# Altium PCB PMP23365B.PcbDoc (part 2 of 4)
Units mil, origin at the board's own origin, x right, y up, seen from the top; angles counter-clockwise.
Board outline 5450 x 2600 mil, 4 copper layers (Top Layer, Signal Layer 1, Signal Layer 2, Bottom Layer), stack 61.2 mil thick; 303 components, 149 nets, 783 pads, 285 vias.
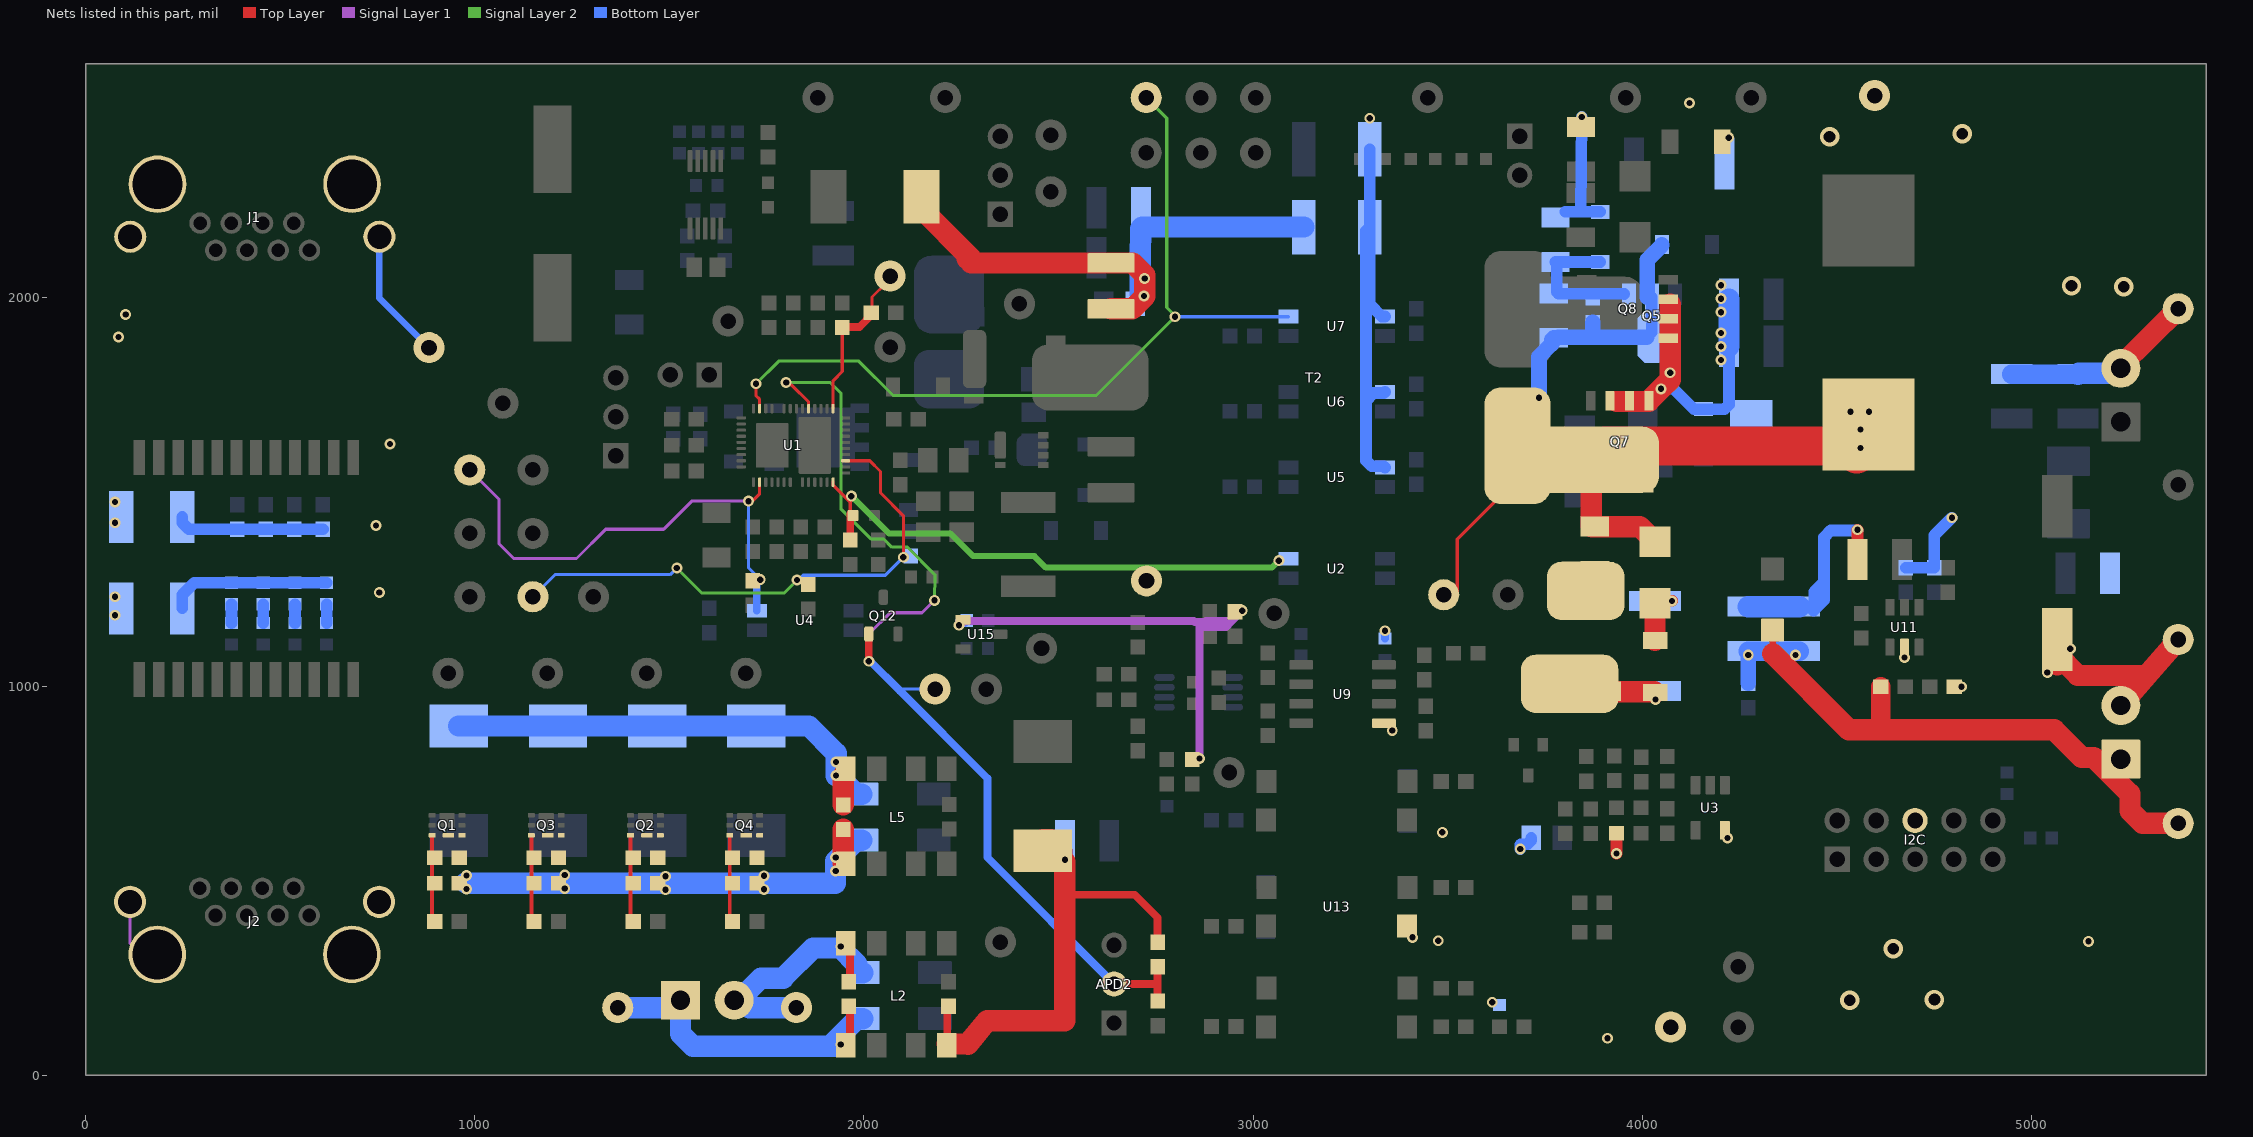
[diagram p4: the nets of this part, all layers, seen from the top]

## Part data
"5V Out" Adapter: "Terminal Block, 3.5mm Pitch, 2x1, TH", Color=Grey, Current_A=6A, Manufacturer="On-Shore Technology", PartNumber=ED555/2DS, Supplier Part Number 1=ED1514-ND, Voltage_V=150V
5V_REG VLOAD: library part CMP-0055137-2, "Test Point, Miniature, Red, TH", Color=Red, Manufacturer="Keystone Electronics", PartNumber=5000, Supplier Part Number 1=36-5000-ND
ad+ PR12: library part CMP-0055137-1, "Test Point, Miniature, Red, TH", Color=Red, Manufacturer=Keystone, Supplier Part Number 1=36-5000-ND
ad- EARTH PR36: library part CMP-0055138-1, "Test Point, Miniature, Black, TH", Color=Black, Manufacturer=Keystone, Supplier Part Number 1=36-5001-ND
APD1 BT DEN LUV PR45 REF SCL_at_pri SCL_pri SCL_pri_raw SDA_at_pri SDA_pri SDA_pri_raw TPH TPL: library part CMP-0055139-1, "Test Point, Miniature, White, TH", Color=White, Manufacturer=Keystone, Supplier Part Number 1=36-5002-ND
APD2 DIT I2C_pri: library part CMP-0054951-1, "Header, 100mil, 3x1, Tin, TH", Manufacturer="TE Connectivity", Supplier Part Number 1=5-146278-3-ND
C1 C2 C3 C4: library part CMP-0007468-5, "CAP, CERM, 0.01 uF, 100 V, +/- 10%, X7R, 0603", Cap_Case=0603, Manufacturer=MuRata, PartNumber=GRM188R72A103KA01D, Supplier Part Number 1=GRM188R72A103KA01D-ND, TempCo=X7R, Tolerance_%=10%, Value1=Unknown, Value2=100V, ValueDisplayed=0.01uF
C5 C6: library part CMP-0009438-2, "CAP, CERM, 1000 pF, 2000 V, +/- 10%, X7R, 1812", Cap_Case=1812, Manufacturer=MuRata, TempCo=X7R, Tolerance_%=10%, Value1=Unknown, Value2=2000V, ValueDisplayed=1000pF
C7 C8 C10 C11: library part CMP-0007053-4, "CAP, CERM, 1000 pF, 100 V, +/- 10%, X7R, 0603", Cap_Case=0603, Manufacturer=TDK, Supplier Part Number 1=445-1298-1-ND, TempCo=X7R, Tolerance_%=10%, Value1=Unknown, Value2=100V, ValueDisplayed=1000pF
C9: library part CMP-0009232-2, "CAP, CERM, 2.2 uF, 100 V, +/- 10%, X7R, 1210", Cap_Case=1210, Manufacturer=MuRata, PartNumber=GRM32ER72A225KA35L, Supplier Part Number 1=490-3385-1-ND, TempCo=X7R, Tolerance_%=10%, Value1="0.007 ohm", Value2=100V, ValueDisplayed=2.2uF
C12 C13 C14 C15: library part CMP-0007209-4, "CAP, CERM, 330 pF, 50 V, +/- 5%, C0G/NP0, 0603", Cap_Case=0603, Manufacturer=MuRata, Supplier Part Number 1=490-1439-1-ND, TempCo=C0G/NP0, Tolerance_%=5%, Value1=Unknown, Value2=50V, ValueDisplayed=330pF
C16 C18: library part CMP-0009358-2, "CAP, CERM, 2200 pF, 2000 V, +/- 10%, X7R, 1812", Cap_Case=1812, Manufacturer=TDK, Supplier Part Number 1=445-2389-1-ND, TempCo=X7R, Tolerance_%=10%, Value1=Unknown, Value2=2000V, ValueDisplayed=2200pF
C17 C31 C40: library part CMP-0008975-2, "CAP, CERM, 0.047 uF, 250 V, +/- 10%, X7R, 1206", Cap_Case=1206, Manufacturer=MuRata, Supplier Part Number 1=490-3538-1-ND, TempCo=X7R, Tolerance_%=10%, Value1=Unknown, Value2=250V, ValueDisplayed=0.047uF
C19: library part CMP-0009053-2, "CAP, CERM, 470 pF, 500 V, +/- 10%, X7R, 1206", Cap_Case=1206, Manufacturer=Vishay-Vitramon, Supplier Part Number 1=720-1076-1-ND, TempCo=X7R, Tolerance_%=10%, Value1=Unknown, Value2=500V, ValueDisplayed=470pF
C20 C33: library part CMP-0008881-2, "CAP, CERM, 0.1 uF, 100 V, +/- 10%, X7R, 1206", Cap_Case=1206, Manufacturer=MuRata, Supplier Part Number 1=490-3364-1-ND, TempCo=X7R, Tolerance_%=10%, Value1=Unknown, Value2=100V, ValueDisplayed=0.1uF
C21: library part CMP-0011231-3, "CAP, AL, 68 uF, 100 V, +/- 20%, SMD", Cap_Case=KE0, Manufacturer=Chemi-Con, Tolerance_%=20%, Value1=Unknown, Value2=100V, ValueDisplayed=68uF
C22 C23 C24: library part CMP-0009232-2, "CAP, CERM, 2.2 uF, 100 V, +/- 10%, X7R, 1210", Cap_Case=1210, Manufacturer=MuRata, Supplier Part Number 1=490-3385-1-ND, TempCo=X7R, Tolerance_%=10%, Value1="0.007 ohm", Value2=100V, ValueDisplayed=2.2uF
C25: library part CMP-0008363-2, "CAP, CERM, 0.1 uF, 100 V, +/- 10%, X7R, 0805", Cap_Case=0805, Manufacturer=MuRata, Supplier Part Number 1=490-12005-1-ND, TempCo=X7R, Tolerance_%=10%, Value1=Unknown, Value2=100V, ValueDisplayed=0.1uF
C26 C32 C44: library part CMP-0007130-4, "CAP, CERM, 100 pF, 100 V, +/- 5%, C0G/NP0, AEC-Q200 Grade 1, 0603", Cap_Case=0603, Manufacturer=MuRata, Supplier Part Number 1=490-4771-1-ND, TempCo=C0G/NP0, Tolerance_%=5%, Value1=Unknown, Value2=100V, ValueDisplayed=100pF
C27 C29 C55 C56 C57 C62: library part CMP-0009214-2, "CAP, CERM, 10 uF, 50 V, +/- 10%, X5R, 1210", Cap_Case=1210, Manufacturer=MuRata, Supplier Part Number 1=490-8590-1-ND, TempCo=X5R, Tolerance_%=10%, Value1=Unknown, Value2=50V, ValueDisplayed=10uF
C30: library part CMP-0008336-2, "CAP, CERM, 1 uF, 25 V, +/- 10%, X7R, 0805", Cap_Case=0805, Manufacturer=MuRata, Supplier Part Number 1=GRM21BR71E105KA99L-ND, TempCo=X7R, Tolerance_%=10%, Value1=Unknown, Value2=25V, ValueDisplayed=1uF
C34 C48: library part CMP-0007457-4, "CAP, CERM, 0.047 uF, 50 V, +/- 10%, X7R, 0603", Cap_Case=0603, Manufacturer=MuRata, Supplier Part Number 1=490-3287-1-ND, TempCo=X7R, Tolerance_%=10%, Value1=Unknown, Value2=50V, ValueDisplayed=0.047uF
C35: library part CMP-0009046-1, "CAP, CERM, 220 pF, 500 V, +/- 10%, X7R, 1206", Cap_Case=1206, Manufacturer=Vishay-Vitramon, Supplier Part Number 1=720-1023-1-ND, TempCo=X7R, Tolerance_%=10%, Value1=Unknown, Value2=500V, ValueDisplayed=220pF
C36: library part CMP-0007885-1, "CAP, CERM, 4.7 uF, 35 V, +/- 10%, X7R, 0805", Cap_Case=0805, Manufacturer=TDK, Supplier Part Number 1=445-7555-1-ND, TempCo=X7R, Tolerance_%=10%, Value1="0.002346 ohm", Value2=35V, ValueDisplayed=4.7uF
C37: library part CMP-0008021-2, "CAP, CERM, 0.1 uF, 50 V, +/- 10%, X7R, AEC-Q200 Grade 1, 0805", Cap_Case=0805, Manufacturer=MuRata, Supplier Part Number 1=490-8049-1-ND, TempCo=X7R, Tolerance_%=10%, Value1=Unknown, Value2=50V, ValueDisplayed=0.1uF
C38: library part CMP-0007835-2, "CAP, CERM, 0.22 uF, 50 V, +/- 10%, X5R, 0805", Cap_Case=0805, Manufacturer=TDK, Supplier Part Number 1=445-14405-1-ND, TempCo=X5R, Tolerance_%=10%, Value1="0.016949 ohm", Value2=50V, ValueDisplayed=0.22uF
C39 C42: library part CMP-0007077-5, "CAP, CERM, 0.1 uF, 25 V, +/- 10%, X7R, AEC-Q200 Grade 1, 0603", Cap_Case=0603, Manufacturer=TDK, Supplier Part Number 1=445-5667-1-ND, TempCo=X7R, Tolerance_%=10%, Value1=Unknown, Value2=25V, ValueDisplayed=0.1uF
C41: library part CMP-0006897-4, "CAP, CERM, 2200 pF, 50 V, +/- 10%, X7R, 0603", Cap_Case=0603, Manufacturer=Kemet, Supplier Part Number 1=1362428, TempCo=X7R, Tolerance_%=10%, Value1=Unknown, Value2=50V, ValueDisplayed=2200pF
C43: library part CMP-0007220-4, "CAP, CERM, 47 pF, 50 V, +/- 5%, C0G/NP0, 0603", Cap_Case=0603, Manufacturer=MuRata, Supplier Part Number 1=490-1419-1-ND, TempCo=C0G/NP0, Tolerance_%=5%, Value1=Unknown, Value2=50V, ValueDisplayed=47pF
C45: library part CMP-0094554-1, "Multilayer Ceramic Capacitors 68nF ±20% 25V X8R SMD 0603", Manufacturer=TDK, Operating Temperature Range="-55°C to +150°C", TempCo=0.15, Temperature Characteristic=X8R, Tolerance_%=0.2%, ValueDisplayed=68nF, Voltage=50V
C46: library part CMP-0006978-4, "CAP, CERM, 0.01 uF, 50 V, +/- 10%, X7R, 0603", Cap_Case=0603, Manufacturer=Kemet, Supplier Part Number 1=399-5346-1-ND, TempCo=X7R, Tolerance_%=10%, Value1=Unknown, Value2=50V, ValueDisplayed=0.01uF
C47: library part CMP-0007873-2, "CAP, CERM, 1 uF, 50 V, +/- 10%, X7R, 0805", Cap_Case=0805, Manufacturer=TDK, Supplier Part Number 1=445-7547-1-ND, TempCo=X7R, Tolerance_%=10%, Value1="0.008782 ohm", Value2=50V, ValueDisplayed=1uF
C49 C61: library part CMP-0006837-3, "CAP, CERM, 0.1 uF, 50 V, +/- 10%, X7R, 0603", Cap_Case=0603, Manufacturer="Wurth Elektronik", TempCo=X7R, Tolerance_%=10%, Value1=Unknown, Value2=50V, ValueDisplayed=0.1uF
C51 C52 C53 C65 C66 C67 C68 C70: library part CMP-0079720-1, "CAP, CERM, 1 µF, 25 V,+/- 10%, X7R, 0603", Cap_Case=0603, Manufacturer=MuRata, Supplier Part Number 1=490-10888-1-ND, TempCo=X7R, Tolerance_%=10%, Value2=25V, ValueDisplayed=1µF
C58: library part CMP-0064994-2, "CAP, Polymer Hybrid, 100 uF, 50 V,+/- 20%, 0.028 ohm, AEC-Q200 Grade 1, D10xL10.2mm SMD", Cap_Case=10x10.2mm, Manufacturer=Panasonic, Supplier Part Number 1=P15462CT-ND, Tolerance_%=20%, Value1="0.028 ohm", Value2=50V, ValueDisplayed=100uF
C59 C60: library part CMP-0009224-2, "CAP, CERM, 22 uF, 25 V, +/- 10%, X7R, 1210", Cap_Case=1210, Manufacturer=MuRata, Supplier Part Number 1=490-5313-1-ND, TempCo=X7R, Tolerance_%=10%, Value1=Unknown, Value2=25V, ValueDisplayed=22uF
C63 C64: library part CMP-0007508-5, "CAP, CERM, 1 uF, 50 V, +/- 10%, X7R, 0603", Cap_Case=0603, Manufacturer="Taiyo Yuden", Supplier Part Number 1=587-3247-1-ND, TempCo=X7R, Tolerance_%=10%, Value1=Unknown, Value2=50V, ValueDisplayed=1uF
COMP CS DTHR SST VB: library part CMP-0055139-2, "Test Point, Miniature, White, TH", Color=White, Manufacturer="Keystone Electronics", Supplier Part Number 1=36-5002-ND
D1: library part CMP-0028411-1, "Diode, Schottky, 100 V, 3 A, SMC", Manufacturer="Diodes Inc.", Supplier Part Number 1=B3100-FDICT-ND, Value1=3A, Value2=0.79V
D2 D3 D4 D5: library part CMP-0028623-2, "Diode, Schottky, 100 V, 3 A, SMC", Manufacturer=Vishay-Semiconductor, Value1=3A, Value2=0.62V
D10: library part CMP-0005708-3, "Diode, TVS, Uni, 150 V, 243 Vc, SMC", Manufacturer="Micro Commercial Components", Value1=1500W
D11 D12 D19: library part CMP-0029023-2, "Diode, Superfast Rectifier, 150 V, 1 A, SMA", Manufacturer="Diodes Inc.", Value1=1A, Value2=0.92V
D13: library part CMP-0076993-2, "Diode, Fast Rectifier, 200 V, 0.8 A, SOD-123", Manufacturer=Rohm, Value1=0.8A, Value2=0.95V
D14 D15 D18 D21: library part CMP-0076981-2, "Diode, Switching, 100 V, 0.2 A, SOD-123", Manufacturer="ON Semiconductor", Value1=0.2A, Value2=V
D16 D17 D26: library part CMP-0005751-4, "Diode, Zener, 12 V, 500 mW, SOD-123", Manufacturer="Diodes Inc.", Power_W=500mW, Value1=0.5W
D22: library part CMP-0096356-1, "Diode Array 1 Pair Series Connection Schottky 70 V 200mA (DC) Surface Mount TO-236-3, SC-59, SOT-23-3", Digikey Part Number=BAS70-04-E3-18GICT-ND, Forward Current=200mA, Manufacturer=Vishay, Max Surge Forward Current=600mA, Mouser Part Number=78-BAS70-04-E3-18, Operating Temperature Range="-55°C to +125°C", Peak Reverse Current=0.02uA, ValueDisplayed=1.5pF
D23 D24 D25 D27: library part CMP-0002892-3, "LED, Yellow, SMD", Color=yellow, Manufacturer="Wurth Elektronik", Value1=W, Value2=2V
D29 D30: library part CMP-0080707-2, "Diode, Schottky, 20 V, 0.5 A, SOD-123", Manufacturer="Diodes Inc.", Value1=0.5A, Value2=0.33V
Drain_F Drain_M Drain_P Drain_R Gate_ex Gate_F Gate_M Gate_P Gate_R PR78: library part CMP-0055140-1, "Test Point, Miniature, Orange, TH", Color=Orange, Manufacturer=Keystone, Supplier Part Number 1=36-5003-ND
EMPS TPH/TPL/BT: library part CMP-0054952-1, "Header, 100mil, 2x1, Tin, TH", Manufacturer="TE Connectivity", Supplier Part Number 1=5-146278-2-ND
GND1 GND2 GND3 RTN1 RTN2 RTN3 VSS1 VSS2: library part CMP-0055138-2, "Test Point, Miniature, Black, TH", Color=Black, Manufacturer="Keystone Electronics", Supplier Part Number 1=36-5001-ND
GND4 RTN4: library part CMP-0055138-2, "Test Point, Miniature, Black, TH", Color=Black, Manufacturer="Keystone Electronics", PartNumber=5001, Supplier Part Number 1=36-5001-ND
H1 H2 H3 H4: library part CMP-0003620-1, "Bumpon, Hemisphere, 0.44 X 0.20, Clear", Manufacturer=3M, Supplier Part Number 1=SJ5303-7-ND
I2C: library part CMP-0055448-2, "Header (shrouded), 100mil, 5x2, High-Temperature, Gold, TH", Manufacturer=3M, Supplier Part Number 1=MHC10K-ND
J1 J2: library part CMP-0054918-1, "RJ45, No LED, tab up, R/A, TH", Color=Black, Manufacturer="TE Connectivity", Supplier Part Number 1=A97716-ND
L1 L3 L4 L6: library part CMP-0003134-1, "Ferrite Bead, 180 ohm @ 100 MHz, 3.1 A, 0805", Manufacturer="Wurth Elektronik", Supplier Part Number 1=732-6123-1-ND, Value1="0.0265 ohm", Value2=3.1A, ValueDisplayed="180 ohm"
L2 L5: library part CMP-0094039-1, "Common Mode Choke Power 700Ω 4A -40 to 125°C Wire Wound Surface Mount T/R", Digikey Part Number=240-2978-1-ND, Impedance At Frequency="700Ω @ 100MHz", Manufacturer=Laird, Mouser Part Number=739-CM7060P701R-10, Operating Temperature Range="-40°C to +125°C"
L7: library part CMP-0059863-1, "Inductor, Drum Core, Ferrite, 4.7 uH, 6.5 A, 0.023 ohm, SMD", Manufacturer=Cyntec, Value1="0.023 ohm", Value2=6.5A, ValueDisplayed=4.7uH
L8: library part CMP-0064480-2, "Inductor, Shielded Drum Core, Ferrite, 47 uH, 6.8 A, 0.0335 ohm, SMD", Manufacturer="Wurth Elektronik", Supplier Part Number 1=732-2179-1-ND, Value1="0.0335 ohm", Value2=6.8A, ValueDisplayed=47uH
L9: library part CMP-0061681-2, "Inductor, Drum Core, Ferrite, 1 mH, 0.1 A, 13.8 ohm, SMD", Manufacturer=Coilcraft, Value1="13.8 ohm", Value2=0.1A, ValueDisplayed=1mH
L10: library part CMP-0063313-2, "Inductor, Shielded Drum Core, Powdered Iron, 1 uH, 6.5 A, 0.011 ohm, SMD", Manufacturer=Vishay-Dale, Supplier Part Number 1=541-1234-1-ND, Value1="0.011 ohm", Value2=6.5A, ValueDisplayed=1uH
L11: library part CMP-0080041-1, "Inductor, Shielded, Ferrite, 15 µH, 2.4 A, 0.078 ohm, SMD", Manufacturer=MuRata, PartNumber=1273AS-H-150M{}P3, Supplier Part Number 1=490-10838-1-ND, Value1="0.078 ohm", Value2=2.4A, ValueDisplayed=15µH
Logo1: library part CMP-0074847-1, "FCC_disclaimer"
Logo2: library part CMP-0074769-1
OUT: library part CMP-0074913-1, "Terminal Block, 3.5mm Pitch, 2x1, TH", Color=Grey, Current_A=6A, Manufacturer="On-Shore Technology", Supplier Part Number 1=ED1514-ND, Voltage_V=150V
Q1 Q2 Q3 Q4: library part CMP-0000968-2, "MOSFET, N-CH, 100 V, 4.5 A, DQK0006C (WSON-6)", Alternate Manufacturer=None, Manufacturer="Texas Instruments"
Q5 Q6: library part CMP-0000510-2, "Transistor, NPN, 150 V, 1 A, AEC-Q101, SOT-89", Manufacturer="Diodes Inc.", Supplier Part Number 1=FCX495CT-ND, Value1="1 A", Value2=300
Q7 Q8: library part CMP-0001056-1, "MOSFET, N-CH, 150 V, 35 A, PQFN08A", Alternate Manufacturer=None, Manufacturer="Fairchild Semiconductor", Supplier Part Number 1=FDMS86200CT-ND, Value2="33 nC"
Q9: library part CMP-0000056-3, "MOSFET, P-CH, -150 V, -3 A, QFN-8", Alternate Manufacturer=None, Manufacturer="Fairchild Semiconductor", Value2="6.2 nC"
Q10: library part CMP-0001057-1, "MOSFET, N-CH, 150 V, 6.7 A, PQFN08A", Alternate Manufacturer=None, Manufacturer="Fairchild Semiconductor", Supplier Part Number 1=FDMS86250CT-ND, Value1=0.02, Value2="36 nC"
Q11: library part CMP-0000985-1, "MOSFET, N-CH, 100 V, 26 A, PowerPAK SO-8", Alternate Manufacturer=None, Manufacturer="Fairchild Semiconductor", Supplier Part Number 1=FDMS86105CT-ND, Value1=0.03, Value2="4.2 nC"
Q12: library part CMP-0000769-1, "MOSFET, N-CH, 60 V, 0.17 A, SOT-23", Alternate Manufacturer=None, Manufacturer="Diodes Inc.", Supplier Part Number 1=2N7002-FDICT-ND, Value1=7, Value2="223 nC"
R1 R2 R3 R4: library part CMP-0022590-4, "RES, 75.0, 1%, 0.1 W, AEC-Q200 Grade 0, 0603", Manufacturer=Vishay-Dale, PartNumber=CRCW060375R0FKEA, Power_W=100mW, Supplier Part Number 1=541-75.0HCT-ND, TempCo="100 ppm/C", Tolerance_%=1%, Value2=0.1W, Value_Code=75R0, ValueDisplayed=75.0
R5 R6 R7 R8: library part CMP-0023268-5, "RES, 75.0, 1%, 0.1 W, 0603", Manufacturer=Yageo, Power_W=100mW, Supplier Part Number 1=311-75.0HRCT-ND, TempCo="100 ppm/C", Tolerance_%=1%, Value2=0.1W, Value_Code=75R0, ValueDisplayed=75.0
R9 R12 R13 R18 R122: library part CMP-0020802-2, "RES, 0, 5%, 0.125 W, 0805", Manufacturer=Rohm, Power_W=125mW, Supplier Part Number 1=RHM0.0ARCT-ND, TempCo="400 ppm/C", Tolerance_%=5%, Value2=0.125W, Value_Code=0000, ValueDisplayed=0
R10 R59 R88: library part CMP-0021990-4, "RES, 100 k, 1%, 0.1 W, AEC-Q200 Grade 0, 0603", Manufacturer=Vishay-Dale, Power_W=100mW, Supplier Part Number 1=541-100KHCT-ND, TempCo="100 ppm/C", Tolerance_%=1%, Value2=0.1W, Value_Code=100k
R11 R31 R53 R54: library part CMP-0021998-4, "RES, 10.0 k, 1%, 0.1 W, AEC-Q200 Grade 0, 0603", Manufacturer=Vishay-Dale, Power_W=100mW, Supplier Part Number 1=541-10.0KHCT-ND, TempCo="100 ppm/C", Tolerance_%=1%, Value2=0.1W, Value_Code=10k0, ValueDisplayed=10.0k
R14 R15 R16 R17: "RES, 1.00 M, 1%, 0.1 W, AEC-Q200 Grade 0, 0603", Manufacturer=Vishay-Dale, PartNumber=CRCW06031M00FKEA, Power_W=100mW, Supplier Part Number 1=541-1.00MHCT-ND, TempCo="100 ppm/C", Tolerance_%=1%, Value2=0.1W, Value_Code=1M00, ValueDisplayed=1.00M
R19 R20 R21 R22: "RES, 232 k, 1%, 0.1 W, AEC-Q200 Grade 0, 0603", Manufacturer=Vishay-Dale, PartNumber=CRCW0603232KFKEA, Power_W=100mW, Supplier Part Number 1=541-232KHCT-ND, TempCo="100 ppm/C", Tolerance_%=1%, Value2=0.1W, Value_Code=232k
R23: library part CMP-0015944-1, "RES, 33 k, 5%, 1 W, AEC-Q200 Grade 0, 2512", Manufacturer=Vishay-Dale, Power_W=1W, Supplier Part Number 1=541-33KXCT-ND, TempCo="200 ppm/C", Tolerance_%=5%, Value_Code=33k0, ValueDisplayed=33k
R24: library part CMP-0015978-3, "RES, 51, 5%, 1 W, AEC-Q200 Grade 0, 2512", Manufacturer=Vishay-Dale, Power_W=1W, Supplier Part Number 1=541-51XCT-ND, TempCo="200 ppm/C", Tolerance_%=5%, Value_Code=51R0, ValueDisplayed=51
R25: library part CMP-0018576-1, "RES, 10 k, 5%, 0.25 W, 1206", Manufacturer=Vishay-Dale, Power_W=250mW, Supplier Part Number 1=541-10KECT-ND, TempCo="200 ppm/C", Tolerance_%=5%, Value2=0.25W, Value_Code=10k0, ValueDisplayed=10k
R26 R72 R73 R74 R75 R76 R101 R108 R109: library part CMP-0080488-1, "RES, 10.0 k, 1%, 0.1 W, 0603", Manufacturer="TT Electronics/IRC", Power_W=100mW, TempCo="100 ppm/C", Tolerance_%=1%, Value2=0.1W, Value_Code=10k0, ValueDisplayed=10.0k
R27: library part CMP-0018688-2, "RES, 4.3 k, 5%, 0.25 W, 1206", Manufacturer=Vishay-Dale, Power_W=250mW, Supplier Part Number 1=541-4.3KECT-ND, TempCo="200 ppm/C", Tolerance_%=5%, Value2=0.25W, Value_Code=4k30, ValueDisplayed=4.3k
R28: library part CMP-0016779-2, "RES, 20.0 k, 1%, 0.25 W, 1206", Manufacturer=Vishay-Dale, Power_W=250mW, Supplier Part Number 1=541-20.0KFCT-ND, TempCo="100 ppm/C", Tolerance_%=1%, Value2=0.25W, Value_Code=20k0, ValueDisplayed=20.0k
R29: library part CMP-0018659-1, "RES, 33, 5%, 0.25 W, 1206", Manufacturer=Vishay-Dale, Power_W=250mW, Supplier Part Number 1=541-33ECT-ND, TempCo="200 ppm/C", Tolerance_%=5%, Value2=0.25W, Value_Code=33R0, ValueDisplayed=33
R30: library part CMP-0022931-4, "RES, 237 k, 1%, 0.1 W, 0603", Manufacturer=Yageo, Power_W=100mW, Supplier Part Number 1=311-237KHRCT-ND, TempCo="100 ppm/C", Tolerance_%=1%, Value2=0.1W, Value_Code=237k
R32: library part CMP-0022532-4, "RES, 60.4 k, 1%, 0.1 W, AEC-Q200 Grade 0, 0603", Manufacturer=Vishay-Dale, Power_W=100mW, Supplier Part Number 1=541-60.4KHCT-ND, TempCo="100 ppm/C", Tolerance_%=1%, Value2=0.1W, Value_Code=60k4, ValueDisplayed=60.4k
R33: library part CMP-0015868-3, "RES, 10 k, 5%, 1 W, AEC-Q200 Grade 0, 2512", Manufacturer=Vishay-Dale, Power_W=1W, Supplier Part Number 1=541-10KXCT-ND, TempCo="200 ppm/C", Tolerance_%=5%, Value_Code=10k0, ValueDisplayed=10k
R34 R36: library part CMP-0025703-4, "RES, 10, 5%, 0.1 W, AEC-Q200 Grade 0, 0603", Manufacturer=Vishay-Dale, Power_W=100mW, Supplier Part Number 1=541-10GCT-ND, TempCo="200 ppm/C", Tolerance_%=5%, Value2=0.1W, Value_Code=10R0, ValueDisplayed=10
R35: library part CMP-0022447-4, "RES, 49.9 k, 1%, 0.1 W, AEC-Q200 Grade 0, 0603", Manufacturer=Vishay-Dale, Power_W=100mW, Supplier Part Number 1=541-49.9KHCT-ND, TempCo="100 ppm/C", Tolerance_%=1%, Value2=0.1W, Value_Code=49k9, ValueDisplayed=49.9k
R37: library part CMP-0023027-4, "RES, 31.6, 1%, 0.1 W, 0603", Manufacturer=Yageo, Power_W=100mW, Supplier Part Number 1=311-31.6HRCT-ND, TempCo="100 ppm/C", Tolerance_%=1%, Value2=0.1W, Value_Code=31R6, ValueDisplayed=31.6
R38: library part CMP-0023123-5, "RES, 45.3, 1%, 0.1 W, 0603", Manufacturer=Yageo, Power_W=100mW, Supplier Part Number 1=311-45.3HRCT-ND, TempCo="100 ppm/C", Tolerance_%=1%, Value2=0.1W, Value_Code=45R3, ValueDisplayed=45.3
R39: library part CMP-0082530-1, "RES, 100 k, 5%, 0.1 W, 0603", Manufacturer=Vishay-Dale, Power_W=100mW, Supplier Part Number 1=541-3992-1-ND, TempCo="200 ppm/C", Tolerance_%=5%, Value2=0.1W, Value_Code=100k
R40: library part CMP-0023000-5, "RES, 2.00 k, 1%, 0.1 W, 0603", Manufacturer=Yageo, Power_W=100mW, Supplier Part Number 1=311-2.00KHRCT-ND, TempCo="100 ppm/C", Tolerance_%=1%, Value2=0.1W, Value_Code=2k00, ValueDisplayed=2.00k
R41: library part CMP-0022965-5, "RES, 27.4 k, 1%, 0.1 W, 0603", Manufacturer=Yageo, Power_W=100mW, Supplier Part Number 1=311-27.4KHRCT-ND, TempCo="100 ppm/C", Tolerance_%=1%, Value2=0.1W, Value_Code=27k4, ValueDisplayed=27.4k
R42: library part CMP-0017281-2, "RES, 0.05, 1%, 1 W, AEC-Q200 Grade 0, 1206", Manufacturer=Panasonic, Power_W=1W, Supplier Part Number 1=P0.05BVCT-ND, TempCo="50 ppm/C", Tolerance_%=1%, Value_Code=R050, ValueDisplayed=0.05
R43: library part CMP-0022879-5, "RES, 1.47 k, 1%, 0.1 W, 0603", Manufacturer=Yageo, Power_W=100mW, Supplier Part Number 1=311-1.47KHRCT-ND, TempCo="100 ppm/C", Tolerance_%=1%, Value2=0.1W, Value_Code=1k47, ValueDisplayed=1.47k
R44 R45: library part CMP-0022458-2, "RES, 4.99 k, 1%, 0.1 W, 0603", Manufacturer=Vishay-Dale, Power_W=100mW, Supplier Part Number 1=541-4.99KHCT-ND, TempCo="100 ppm/C", Tolerance_%=1%, Value2=0.1W, Value_Code=4k99, ValueDisplayed=4.99k
R46: library part CMP-0022268-4, "RES, 2.00 k, 1%, 0.1 W, AEC-Q200 Grade 0, 0603", Manufacturer=Vishay-Dale, Power_W=100mW, Supplier Part Number 1=541-2.00KHCT-ND, TempCo="100 ppm/C", Tolerance_%=1%, Value2=0.1W, Value_Code=2k00, ValueDisplayed=2.00k
R47: library part CMP-0022410-4, "RES, 40.2 k, 1%, 0.1 W, AEC-Q200 Grade 0, 0603", Manufacturer=Vishay-Dale, Power_W=100mW, Supplier Part Number 1=541-40.2KHCT-ND, TempCo="100 ppm/C", Tolerance_%=1%, Value2=0.1W, Value_Code=40k2, ValueDisplayed=40.2k
R48 R55: library part CMP-0022544-4, "RES, 64.9 k, 1%, 0.1 W, AEC-Q200 Grade 0, 0603", Manufacturer=Vishay-Dale, Power_W=100mW, Supplier Part Number 1=541-64.9KHCT-ND, TempCo="100 ppm/C", Tolerance_%=1%, Value2=0.1W, Value_Code=64k9, ValueDisplayed=64.9k
R49 R98 R99 R104: library part CMP-0022109-5, "RES, 1.00 k, 1%, 0.1 W, AEC-Q200 Grade 0, 0603", Manufacturer=Vishay-Dale, Power_W=100mW, Supplier Part Number 1=541-1.00KHCT-ND, TempCo="100 ppm/C", Tolerance_%=1%, Value2=0.1W, Value_Code=1k00, ValueDisplayed=1.00k
R50: library part CMP-0022445-4, "RES, 499 k, 1%, 0.1 W, AEC-Q200 Grade 0, 0603", Manufacturer=Vishay-Dale, Power_W=100mW, Supplier Part Number 1=541-499KHCT-ND, TempCo="100 ppm/C", Tolerance_%=1%, Value2=0.1W, Value_Code=499k
R51: library part CMP-0022008-4, "RES, 110 k, 1%, 0.1 W, AEC-Q200 Grade 0, 0603", Manufacturer=Vishay-Dale, Power_W=100mW, Supplier Part Number 1=541-110KHCT-ND, TempCo="100 ppm/C", Tolerance_%=1%, Value2=0.1W, Value_Code=110k
R52: library part CMP-0023151-1, "RES, 4.64 k, 1%, 0.1 W, 0603", Manufacturer="Yageo America", Power_W=100mW, Supplier Part Number 1=311-4.64KHRCT-ND, TempCo="200 ppm/C", Tolerance_%=1%, Value2=0.1W, Value_Code=4k64, ValueDisplayed=4.64k
R60 R61 R62 R63 R64 R65 R95: library part CMP-0025753-1, "RES, 20 k, 5%, 0.1 W, 0603", Manufacturer=Vishay-Dale, Power_W=100mW, Supplier Part Number 1=541-20KGCT-ND, TempCo="200 ppm/C", Tolerance_%=5%, Value2=0.1W, Value_Code=20k0, ValueDisplayed=20k
R66: library part CMP-0021980-1, "RES, 0.01, 1%, 0.25 W, AEC-Q200 Grade 0, 0805", Manufacturer=Vishay-Dale, Power_W=250mW, Supplier Part Number 1=WSLB-.01DKR-ND, TempCo="75 ppm/C", Tolerance_%=1%, Value2=0.25W, Value_Code=R010, ValueDisplayed=0.01
R67 R68: library part CMP-0022908-4, "RES, 20.0, 1%, 0.1 W, 0603", Manufacturer=Yageo, Power_W=100mW, Supplier Part Number 1=311-20.0HRCT-ND, TempCo="100 ppm/C", Tolerance_%=1%, Value2=0.1W, Value_Code=20R0, ValueDisplayed=20.0
R80 R81 R82 R83 R92 R93: library part CMP-0021991-4, "RES, 100, 1%, 0.1 W, AEC-Q200 Grade 0, 0603", Manufacturer=Vishay-Dale, Power_W=100mW, Supplier Part Number 1=541-100HCT-ND, TempCo="100 ppm/C", Tolerance_%=1%, Value2=0.1W, Value_Code=100R, ValueDisplayed=100
R89 R94 R97 R100 R105 R106 R107 R110 R111 R115 R116 R117 R118 R121 R123: library part CMP-0025874-4, "RES, 0, 5%, 0.1 W, AEC-Q200 Grade 0, 0603", Manufacturer=Panasonic, Power_W=100mW, Supplier Part Number 1=P0.0GCT-ND, TempCo="600 ppm/C", Tolerance_%=5%, Value2=0.1W, Value_Code=0000, ValueDisplayed=0
R96: library part CMP-0022106-2, "RES, 19.6 k, 1%, 0.1 W, 0603", Manufacturer=Vishay-Dale, Power_W=100mW, Supplier Part Number 1=541-19.6KHCT-ND, TempCo="100 ppm/C", Tolerance_%=1%, Value2=0.1W, Value_Code=19k6, ValueDisplayed=19.6k
R102: library part CMP-0022816-5, "RES, 15.0 k, 1%, 0.1 W, 0603", Manufacturer=Yageo, Power_W=100mW, Supplier Part Number 1=311-15.0KHRCT-ND, TempCo="100 ppm/C", Tolerance_%=1%, Value2=0.1W, Value_Code=15k0, ValueDisplayed=15.0k
R103: library part CMP-0082533-1, "RES, 4.99 k, 1%, 0.1 W, 0603", Manufacturer=Vishay-Dale, Power_W=100mW, Supplier Part Number 1=541-3985-1-ND, TempCo="100 ppm/C", Tolerance_%=1%, Value2=0.1W, Value_Code=4k99, ValueDisplayed=4.99k
R120: library part CMP-0017248-2, "RES, 0.1, 1%, 0.5 W, 1206", Manufacturer=Bourns, Power_W=500mW, Supplier Part Number 1=652-CRM1206FXR100ELF, TempCo="150 ppm/C", Tolerance_%=1%, Value2=0.5W, Value_Code=R100, ValueDisplayed=0.1
SH-J1 SH-J2 SH-J4: library part CMP-0003761-2, "Shunt, 2.54mm, Gold, Black", Manufacturer="Wurth Elektronik", Supplier Part Number 1=732-2678-ND
T1: library part CMP-0030597-1, "Transformer, 350 uH, SMT", Manufacturer="Wurth Elektronik", ValueDisplayed=350uH
T2: library part CMP-0096341-1, "TRANSFORMER", Frequency_Fixed=250kHz, Manufacturer="Wurth Electronics", Operating Temperature Range="-40°C to +125°C", Voltage_Isolation_Vrms=1.5kV
U1: library part CMP-0860918-1, "TPS23730RMT, RMT0045A (VQFN-45)", Alternate Manufacturer="Texas Instruments"
U2: library part CMP-0006166-3, "Optocoupler, 3.75 kV, 80-160% CTR, SMT", Manufacturer=Vishay-Semiconductor, Supplier Part Number 1=TCMT1107CT-ND, Voltage_Isolation_Vrms=3.75kV
U3: library part CMP-0032888-1, "Adjustable Precision Shunt Regulator, 34 ppm / degC, 100 mA, -40 to 85 degC, 5-pin SOT-23 (DBV), Green (RoHS & no Sb/Br)", Manufacturer="Texas Instruments", Rating=Military, Temp Coeff(Max)(ppm/ degree C)=92, Temp Coeff(Typ)(ppm/ degree C)=34
U4 U5 U6 U7: library part CMP-0079530-1, "Optocoupler, 3.75 kV, 160-320% CTR, SMT", Manufacturer=Vishay-Semiconductor, Supplier Part Number 1=TCMT1104CT-ND, Voltage_Isolation_Vrms=3.75kV
U8: library part CMP-0088571-2, "High-Voltage, Zero-Drift, 16-Bit ADC, I 2C, Bidirectional Shunt Current, Bus Voltage, Power, and Temperature Monitor", Manufacturer="Texas Instruments", Operating Temperature Range=to
U9: library part CMP-0091761-1, "I²C Digital Isolator 3000Vrms 2 Channel  50kV/µs CMTI 8-SOIC (0.154\", 3.90mm Width)", Digikey Part Number=296-ISO1640BDRCT-ND, Manufacturer="Texas Instruments", Max Supply Voltage=5.5V, Min Supply Voltage=2.25V, Mouser Part Number=595-ISO1640BDR, Nominal Supply Current=2.7-5.3mA, Operating Temperature Range="-40°C to +125°C"
U11: library part CMP-0093105-2, "Buck Converter, Adjustable, 4V-36V Input, 1-28V 1A Output, SOT23-6", Manufacturer="Texas Instruments", Max Supply Voltage=36V, Min Supply Voltage=4V, Nominal Supply Current=80uA, Operating Temperature Range="-40°C to +150°C", Output Voltage=1-28V, Switching Frequency=700kHz
U12 U13 U14: library part CMP-0006165-2, "Optocoupler, 5 kV, 300-600% CTR, SMT", Manufacturer="Fairchild Semiconductor", Supplier Part Number 1=FOD817DS-ND, Voltage_Isolation_Vrms=5kV
U15: library part CMP-0074892-1, "100-mA, 30-V, Fixed-Output, Linear-Voltage Regulator, DBZ0003A (SOT-23-3)", Alternate Manufacturer="Texas Instruments", Alternate PartNumber=TLV76050DBZT
U16: library part CMP-0065788-2, "Level-Translating I2C Bus Repeater, DGK0008A (VSSOP-8)", Alternate Manufacturer="Texas Instruments"
VCC VDD VOUT: library part CMP-0055137-2, "Test Point, Miniature, Red, TH", Color=Red, Manufacturer="Keystone Electronics", Supplier Part Number 1=36-5000-ND

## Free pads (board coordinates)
  rrect50% 180x150 smd far side: 1(2218.74,1788.74)
  rrect50% 180x200 smd far side: 1(2218.74,2006.57)
  rrect50% 60x150 smd: 1(2284.49,1840.81)
  rrect50% 30x70 smd: 1(2350.71,1619.61)
  rrect50% 80x80 smd far side: 1(2432.24,1606.16)
  rrect50% 300x170 smd: 1(2581.66,1793.73)
  rrect50% 170x300 smd: 1(3679.66,1617.92) 1(3679.66,1968.61)
  rrect50% 250x150 smd: 1(3813.84,1006.14)
  rrect50% 340x170 smd: 1(3830,1967.5)
  rrect50% 200x150 smd: 1(3855,1245)
  rrect50% 350x170 smd: 1(3868.75,1582.05)

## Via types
v1: diameter 28, hole 16, Top Layer to Bottom Layer, 261 vias
v2: diameter 19.68, hole 7.87, Top Layer to Bottom Layer, 13 vias
v3: diameter 50, hole 30, Top Layer to Bottom Layer, 7 vias
v4: diameter 50, hole 28, Top Layer to Bottom Layer, 4 vias

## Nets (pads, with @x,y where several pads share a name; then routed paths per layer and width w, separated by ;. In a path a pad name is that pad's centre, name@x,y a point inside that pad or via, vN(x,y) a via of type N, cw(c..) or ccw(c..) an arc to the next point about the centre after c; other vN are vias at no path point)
5V_pri: C70.1 R105.1 R107.1 U15.1 | length 1253.5
  Top Layer w20: v1(2244.75,1156.76) U15.1@2254.75,1170.84
  Signal Layer 1 w20: v1(2244.75,1156.76) 2262.71,1167.41 ; v1@2244.75,1167.41 2847.53,1167.41 2850.05,1164.89 2876.45,1164.89 2878.97,1167.41 2945.63,1167.41 ; v1(2862.4,814.45) 2862.4,1152.11 2862.23,1152.29 2930.51,1152.29 2945.63,1167.41 ; v1(2972.4,1194.18) 2945.63,1167.41
  Bottom Layer w20: C70.1@2264.44,1167.45 2258.69,1161.7 2251.86,1161.7 2246.92,1156.76 v1(2244.75,1156.76) C70.1@2264.44,1168.44
APD: APD1.1 APD2.2 Q12.1 R10.1 R11.2 U1.5 | length 2649.3
  Top Layer w8: v1(1800.25,1780.27) 1805.66,1780.27 1812.08,1773.86 1814.6,1773.86 1857.97,1730.49 1857.97,1713.25 U1.5@1858.1,1713.25
  Top Layer w20: Q12.1@2012.54,1134.14 2012.62,1134.06 2012.62,1064.29 v1(2012.7,1064.21) ; APD2.2@2642.93,234.71 2754.46,234.71 2754.9,235.15 ; R11.2@2754.9,190.87 2754.9,235.15 ; R10.1@2754.9,279.43 2754.9,235.15
  Signal Layer 1 w8: v1(2012.7,1064.21) 2012.7,1134.14 2067.44,1188.88 2149.45,1188.88 v1(2181.33,1220.75)
  Signal Layer 2 w8: v1(1800.25,1780.27) 1914.11,1780.27 1940.77,1753.61 1940.77,1455.87 2017.94,1378.7 2050.58,1378.7 2071.95,1357.33 2112.05,1357.33 2182.52,1286.87 v1(2181.33,1220.75)
  Bottom Layer w8: 2093.17,987.75 2098.14,992.72 APD1.1@2183.03,992.72
  Bottom Layer w20: v1@2016.35,1064.57 2093.17,987.75 2317.35,763.57 2317.35,560.3 APD2.2@2642.93,234.71
BT: BT.1 U1.12 U7.2 | length 2174.1
  Top Layer w8: v1(1722.86,1777.26) 1722.86,1746.32 1732.11,1737.07 U1.12@1732.11,1713.25
  Signal Layer 2 w8: v1(1722.86,1777.26) 1780.88,1835.28 1987.12,1835.28 2075.19,1747.21 2597.13,1747.21 v1(2799.37,1949.45) 2799.37,1952.27 2778.38,1973.26 2778.38,2459.6 BT.1@2725.48,2512.5
  Bottom Layer w8: v1(2799.37,1949.45) 3090.44,1949.45 U7.2@3090.98,1950
COMP: C45.1 COMP.1 R46.1 U1.35 U2.4 | length 1387
  Top Layer w8: U1.35@1921.09,1524.28 1921.09,1516.53 1942.81,1494.8 1943.21,1494.8 1964.87,1473.14 C45.1@1964.87,1442.44
  Top Layer w16: v1(1967.74,1488.44) v1@1970.04,1486.14
  Top Layer w20: R46.1@1964.87,1375.75 C45.1@1964.87,1442.44
  Signal Layer 2 w16: v1(1967.74,1488.44) 1968.95,1488.44 2065.18,1392.2 2222.84,1392.2 2280.63,1334.41 2438.29,1334.41 2467.82,1304.88 COMP.1@2728.51,1304.88 ; COMP.1@2726.35,1270.8 2728.51,1272.96 COMP.1@2728.51,1304.88 ; v1(3066.3,1322.6) 3048.58,1304.88 COMP.1@2728.51,1304.88
CS: C43.1 CS.1 R40.1 U1.1 | length 445
  Top Layer w8: U1.1@1921.09,1713.25 1921.09,1785.32 1944.54,1808.77 C43.1@1944.54,1921.68 ; R40.1@2021.05,1959.99 2021.05,2000.09 2054.68,2033.73 2079.39,2033.73 CS.1@2093.17,2047.5
  Top Layer w20: C43.1@1944.54,1921.68 1946.32,1923.46 1988.97,1923.46 R40.1@2021.05,1955.54
  Top Layer w30: R40.1@2021.05,1955.54 R40.1@2021.05,1959.99
DEN: DEN.1 R41.2 U1.24 U4.4 | length 1302.6
  Top Layer w8: v1(1703.8,1475.51) 1713.09,1475.51 1732.05,1494.46 1732.05,1524.22 U1.24@1732.11,1524.28
  Signal Layer 1 w8: DEN.1@987.3,1555.77 1062.5,1480.58 1062.5,1365.7 1100.06,1328.14 1261.37,1328.14 1336.73,1403.5 1485.58,1403.5 1557.58,1475.51 v1(1703.8,1475.51)
  Bottom Layer w8: v1(1703.8,1475.51) 1703.8,1303.63 v1(1733.64,1273.79)
  Bottom Layer w20: U4.4@1724.95,1193.98 1724.95,1262.93 1733.64,1271.63 v1(1733.64,1273.79)
EARTH: C5.2 C6.2 EARTH.1 J1.9 J1.10 J1.11 J1.12 J2.9 J2.10 J2.11 J2.12 | length 526.6
  Signal Layer 1 w8: J2.10@114.13,445.94 114.13,338.92 115.36,337.69 157.42,337.69 J2.12@184.21,310.9
  Bottom Layer w16: J1.10@754.84,2155.04 754.84,1997.66 EARTH.1@882.5,1870
  other v1: 75.51,1182.24 75.51,1229.93 754.84,1240.82 746.4,1413.35 75.51,1420 75.51,1473.14 782.54,1622.7 84.66,1897.65 102.9,1954.95
GND: "5V Out.2" C16.1 C17.1 C18.1 C27.2 C29.2 C35.1 C40.1 C47.2 C52.2 C55.2 C56.2 C57.2 C58.2 C59.1 C60.1 C62.2 C63.2 C64.2 C66.2 D10.2 D16.2 D17.2 GND1.1 GND2.1 GND3.1 GND4.1 I2C.6 OUT.2 pad.1@3813.84,1006.14 Q7.1 Q7.2 Q7.3 Q8.1 Q8.2 Q8.3 R23.2 R24.2 R28.1 R33.2 R52.1 R96.1 U3.5 U5.3 U6.3 U7.3 U9.5 U11.2 U13.3 | length 4505.9
  Top Layer w20: v1(4673.9,1073.45) 4673.94,1073.5 U11.2@4673.99,1100.55
  Top Layer w30: v1(3934.1,570) R52.1@3934.1,622.32 ; C62.2@4553.46,1325.79 v1(4553.46,1402.19)
  Top Layer w55: R24.2@3878.09,986.97 3879.59,985.47 4031.6,985.47 C17.1@4033.09,983.97 ; 3934.4,1731.68 3967.57,1731.68 Q7.1@4017.57,1731.68 ; Q7.1@4017.57,1733.32 v1(4048.39,1764.15) 4071.96,1787.72 v1(4071.96,1805.47) 4071.96,1981.35 ; C58.2@5066.85,1054.94 C58.2@5066.85,1080.53 ; C58.2@5066.85,1120 C58.2@5066.85,1080.53 ; OUT.2@5223.91,1817.05 5226.97,1820.09 GND2.1@5377.5,1970 ; 5230,950.5 5297.01,1027.51 ; GND4.1@5377.5,1120 5297.01,1027.51 ; C58.2@5066.85,1080.53 5119.87,1027.51 5297.01,1027.51
  Bottom Layer w20: C52.2@3339.02,1122.79 v1(3339.02,1142.48)
  Bottom Layer w30: C16.1@3300,2380 C18.1@3300,2180 ; U5.3@3339.02,1562.22 3336.3,1564.93 3305.41,1564.93 3290.55,1579.79 3290.55,1733.3 ; U6.3@3339.02,1756.11 3336.3,1753.39 3310.64,1753.39 3290.55,1733.3 ; U7.3@3339.02,1950 3331.14,1950 3300,1981.14 C18.1@3300,2180 ; v1(3686.65,581.63) 3686.65,592.43 3687.9,593.67 3705.16,593.67 3715.16,603.67 C47.2@3715.16,610.17 ; R28.1@3802.73,2219.15 3842,2219.15 ; v1(3844.65,2462.74) 3842,2219.15 ; D16.2@3892.14,2219.15 3842,2219.15 ; v1(4048.39,1764.15) 4080.48,1764.15 4133.25,1711.37 4211.44,1711.37 4223.24,1723.17 C27.2@4223.24,1873.69 ; C59.1@4404.31,1204.55 4431.87,1204.55 4442.46,1215.14 4442.46,1242.7 4466.91,1267.15 ; C59.1@4440.51,1194.7 4467.43,1221.63 4467.43,1382.78 4485.01,1400.35 v1@4553.97,1400.35 ; C63.2@4677.31,1304.11 C64.2@4750.52,1304.11 4750.52,1387.54 v1(4795.95,1432.98) ; 3290.55,1733.3 3290.55,2170.55 C18.1@3300,2180
  Bottom Layer w50: C56.2@4949.52,1802.19 C57.2@5120,1802.19
  Bottom Layer w55: C27.2@4223.24,1873.69 C29.2@4223.24,1994.54 ; C60.1@4272.74,1204.55 C59.1@4404.31,1204.55 ; C57.2@5120,1802.19 5121.91,1804.09 5204.87,1804.09 5217.82,1817.05 OUT.2@5230,1817.05
  other v1: 3910.61,95.47 3614.8,187.99 5146.76,344.35 3476.15,345.87 3410.16,354.68 4219.59,610 3486.51,624.49 3357.72,886.3 4034.39,966.02 4820.99,998.7 5041.24,1035.3 5100.32,1096.41 4202.5,1838.17 4202.5,1872.84 4202.5,1907.5 4202.36,1961.23 4202.36,1995.9 4202.36,2030.56 4222.4,2409.64 3300,2459.6 4121.46,2498.72
  other v3: 4533.22,192.82 4751.14,194.81 4645.54,325.5 5237.97,2026.93 5103.36,2029.45 4481.5,2412.05 4822.5,2419.53
LINEUV: LUV.1 R51.1 R53.2 U1.38 | length 1427.4
  Top Layer w8: v1(1828.47,1272.96) 1846.04,1272.96 R51.1@1857.5,1261.5 ; U1.38@1952.58,1579.4 2015.02,1579.4 2042.62,1551.79 2042.62,1497.1 2101.34,1438.39 v1(2101.34,1331.46)
  Signal Layer 2 w8: v1(1519.3,1303.89) 1519.37,1303.89 1583.92,1239.34 1794.86,1239.34 v1(1828.47,1272.96)
  Bottom Layer w8: LUV.1@1149.36,1229.93 1206.31,1286.87 1502.28,1286.87 v1(1519.3,1303.89) ; v1(1828.47,1272.96) 1831.84,1272.96 1844.15,1285.26 2055.14,1285.26 v1(2101.34,1331.46)
"Net5V Out_1": 5V_REG.1 "5V Out.1" C59.2 C60.2 L11.2 R88.2 R123.2 | length 1627.1
  Top Layer w16: 4335.33,1083.8 L11.2@4335.33,1137.33
  Top Layer w50: 4612.98,888.09 4612.98,998.18 R88.2@4613.5,998.7
  Top Layer w55: 4335.33,1083.8 4531.03,888.09 4612.98,888.09 5058.54,888.09 5129.72,816.92 5160,816.92 5253.62,723.3 5253.62,679.72 5285.84,647.5 5V_REG.1@5377.5,647.5
  Bottom Layer w40: R123.2@4272.74,1007.64 C60.2@4272.74,1090.37
  Bottom Layer w50: C60.2@4272.74,1090.37 C59.2@4404.31,1090.37
  other v1: 4272.74,1080.53 4394.38,1080.53
Netad+_1: ad+.1 Adapter.1 C7.1 L2.1 R9.1 | length 869.2
  Top Layer w20: C7.1@1960.75,177.39 1964.11,174.03 1964.11,80.36 R9.1@1967.48,76.99
  Bottom Layer w20: Adapter.1@1509.69,174.02 Adapter.1@1528.73,193.06
  Bottom Layer w55: ad+.1@1367.5,174.02 Adapter.1@1509.69,174.02 ; Adapter.1@1528.73,193.06 1528.73,107.22 1560.95,75 1845,75 1924.78,75 ; 1924.78,82.5 1924.78,87.03 1983.7,145.94 L2.1@1997.48,145.94
  other v1: 1940.45,79.19
Netad-_1: ad-.1 Adapter.2 C7.2 L2.2 R12.1 | length 680.6
  Top Layer w20: C7.2@1960.75,240.39 1964.11,243.75 1964.11,335.51 R12.1@1967.48,338.88
  Bottom Layer w20: Adapter.2@1666.73,193.06 1678.91,193.06 1686.54,193.06 Adapter.2@1705.58,174.02
  Bottom Layer w55: Adapter.2@1678.91,193.06 1735.76,249.9 1792.39,249.9 1869.66,327.18 1939.83,327.18 1981.67,285.34 1981.67,266.08 1983.7,264.06 L2.2@1997.48,264.06 ; Adapter.2@1705.58,174.02 ad-.1@1826.61,174.02
  other v1: 1940.45,331.37
NetC1_2: C1.2 R1.2 | length 47.9
  Bottom Layer w30: C1.2@619.68,1162.56 R1.2@619.68,1210.46
NetC2_2: C2.2 R2.2 | length 47.9
  Bottom Layer w30: C2.2@538.12,1162.56 R2.2@538.12,1210.46
NetC3_2: C3.2 R3.2 | length 47.9
  Bottom Layer w30: C3.2@456.56,1162.56 R3.2@456.56,1210.46
NetC4_2: C4.2 R4.2 | length 47.9
  Bottom Layer w30: C4.2@375,1162.56 R4.2@375,1210.46
NetC5_1: C5.1 R1.1 R2.1 R3.1 R4.1 | length 418.9
  Bottom Layer w30: C5.1@248.74,1200 248.74,1235.43 278.88,1265.58 R4.1@375,1265.58 R3.1@456.56,1265.58 R2.1@538.12,1265.58 R1.1@619.68,1265.58
NetC6_1: C6.1 R5.2 R6.2 R7.2 R8.2 | length 383.1
  Bottom Layer w30: C6.1@248.74,1435 248.74,1420 265.24,1403.5 R5.2@389.39,1403.5 R6.2@462.92,1403.5 R7.2@536.46,1403.5 R8.2@610,1403.5
NetC8_1: C8.1 C9.2 D1.2 L1.2 R10.2 | length 1258.7
  Top Layer w20: L1.2@2210.67,76.99 2214.04,80.36 2214.04,80.99 2214.04,174.02 C8.1@2217.41,177.39 ; 2516.35,463.99 2696.09,463.99 2754.9,405.18 R10.2@2754.9,342.42
  Top Layer w55: L1.2@2214.04,80.99 2267.68,80.36 2317.35,140.71 2516.35,140.71 2516.35,463.99 2516.35,549.65 2508.45,557.56 2508.45,577.56 2480.95,605.06 D1.2@2460.95,605.06
  other v1: 2516.7,554.25
NetC10_1: C10.1 D2.1 D3.1 D4.1 D5.1 L5.2 R13.1 | length 1217.7
  Top Layer w55: C10.1@1946.53,694.97 R13.1@1946.53,770.34
  Bottom Layer w55: D2.1@958.81,897.73 D3.1@1213.81,897.73 D4.1@1468.81,897.73 D5.1@1723.81,897.73 1858.75,897.73 1928.54,827.94 v1(1928.54,770.34) 1933.24,770.34 1981.05,722.53 L5.2@1994.83,722.53
  other v1: 1928.54,805
NetC10_2: C10.2 C12.2 C13.2 C14.2 C15.2 L5.1 Q1.4 Q1.7 Q2.4 Q2.7 Q3.4 Q3.7 Q4.4 Q4.7 R18.1 R19.1 R20.1 R21.1 R22.1 | length 1182.2
  Top Layer w55: R18.1@1946.53,544.37 C10.2@1946.53,631.98
  Bottom Layer w55: 978.5,494.96 979.41,494.04 1926.33,494.04 1926.97,525.35 1927.5,550.87 1981.05,604.42 L5.1@1994.83,604.42
  other v1: 1490.58,477.04 1743.01,478.08 978.81,479.23 1231.24,480.27 1490.58,511.71 1743.01,512.74 978.81,513.9 1231.24,514.93 1927.5,525.34 1927.5,560
NetC12_1: C12.1 Q1.3 R14.1 R19.2 | length 223.5
  Top Layer w10: Q1.3@890.43,616.95 890.43,411.97 ccw(c913.95,411.97) R14.1@897.32,395.34
NetC13_1: C13.1 Q3.3 R15.1 R20.2 | length 223.5
  Top Layer w10: Q3.3@1145.43,616.95 1145.43,411.97 ccw(c1168.95,411.97) R15.1@1152.32,395.34
NetC14_1: C14.1 Q2.3 R16.1 R21.2 | length 223.5
  Top Layer w10: Q2.3@1400.43,616.95 1400.43,411.97 ccw(c1423.95,411.97) R16.1@1407.32,395.34
NetC15_1: C15.1 Q4.3 R17.1 R22.2 | length 223.5
  Top Layer w10: Q4.3@1655.43,616.95 1655.43,411.97 ccw(c1678.95,411.97) R17.1@1662.32,395.34
NetC17_2: C17.2 D11.1 R23.1 | length 141.6
  Top Layer w30: D11.1@4033.09,1213.36 4038.98,1219.25 v1(4076.7,1219.25)
  Top Layer w55: C17.2@4033.09,1117.83 D11.1@4033.09,1213.36
NetC18_2: C18.2 C23.1 C24.1 C25.1 L7.2 T2.1 T2.2 | length 1422.6
  Top Layer w55: L7.2@2147.47,2250.03 2147.47,2227.39 2276.16,2098.69 2265.31,2098.69 ; 2275.66,2087.65 T2.1@2635.06,2087.65 2690.76,2087.65 2721.62,2056.8 v1(2721.62,2047.5) 2721.62,2001.76 2689.4,1969.54 T2.2@2635.06,1969.54
  Bottom Layer w20: C23.1@2711.19,2176 C23.1@2715.19,2180
  Bottom Layer w55: C25.1@2709.91,2003.07 2710.17,2037.73 2710.62,2099.5 2710.63,2100.66 C23.1@2711.19,2176 ; C23.1@2715.19,2180 C18.2@3130,2180
  other v1: 2719.89,2002.99
NetC19_1: C19.1 pad.1@3855,1245 R24.1
NetC19_2: C19.2 C26.2 D10.1 D11.2 D13.1 Drain_R.1 L8.1 pad.1@3679.66,1617.92 pad.1@3868.75,1582.05 Q5.2 Q5.4 Q7.5 Q7.6 Q7.7 Q7.8 R25.2 T2.7 T2.8 T2.9 | length 2387.8
  Top Layer w8: Drain_R.1@3524.84,1234.73 3524.84,1377.84 T2.7@3644.11,1497.1
  Top Layer w30: T2.7@3644.11,1497.1 T2.7@3679.15,1497.1
  Top Layer w55: pad.1@3868.75,1582.05 3868.75,1412.53 3871.09,1410.19 C19.2@3878.09,1410.19 3993.74,1410.19 D11.2@4033.09,1370.84
  Top Layer w75: v1(4561.32,1612.5) 4587.98,1612.5 L8.1@4595.9,1604.58 ; v1(4561.32,1660) 4583.39,1660 L8.1@4617.36,1626.03
  Top Layer w100: pad.1@3868.75,1582.05 3904.62,1617.92 3910.04,1612.5 3914.59,1617.05 4513.3,1617.05 4518.28,1622.02 L8.1@4518.28,1672.89 ; L8.1@4523.69,1672.89 L8.1@4581.41,1672.89 ; L8.1@4551.51,1617.92 L8.1@4551.51,1612.5 ; v1(4561.32,1612.5) L8.1@4551.51,1612.5 ; v1(4561.32,1660) 4551.51,1650.19 4551.51,1597.18 L8.1@4551.51,1612.5
  Bottom Layer w8: Q5.4@4012.09,1896.55 Q5.4@4025,1909.46
  Bottom Layer w30: Q5.4@4025,1909.46 Q5.2@4025,1999.43
  Bottom Layer w40: v1@3735,1742.5 3735,1846.7 3767.45,1879.15 3767.45,1889.98 3773.04,1895.57 3783.87,1895.57 3784.85,1896.55 3873.2,1896.55 ; C26.2@3873.2,1934.7 3873.2,1896.55 ; Q5.4@4012.09,1896.55 3873.2,1896.55 ; Q5.2@4013.08,1999.9 4013.08,2095.52 4050.53,2132.97 D13.1@4050.53,2135
  other v1: 4535.45,1705.33 4582.95,1705.33 3735,1741.27
NetC26_1: C26.1 D16.1 Q5.1 R25.1 R28.2 | length 375.2
  Bottom Layer w8: D16.1@3892.14,2090.21 D16.1@3898.14,2090.21
  Bottom Layer w30: D16.1@3892.14,2090.21 R28.2@3777.14,2090.21 3780.5,2086.85 3780.5,2013.11 3783.87,2009.74 3784.85,2008.76 3953.04,2008.76 Q5.1@3954.02,2007.78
